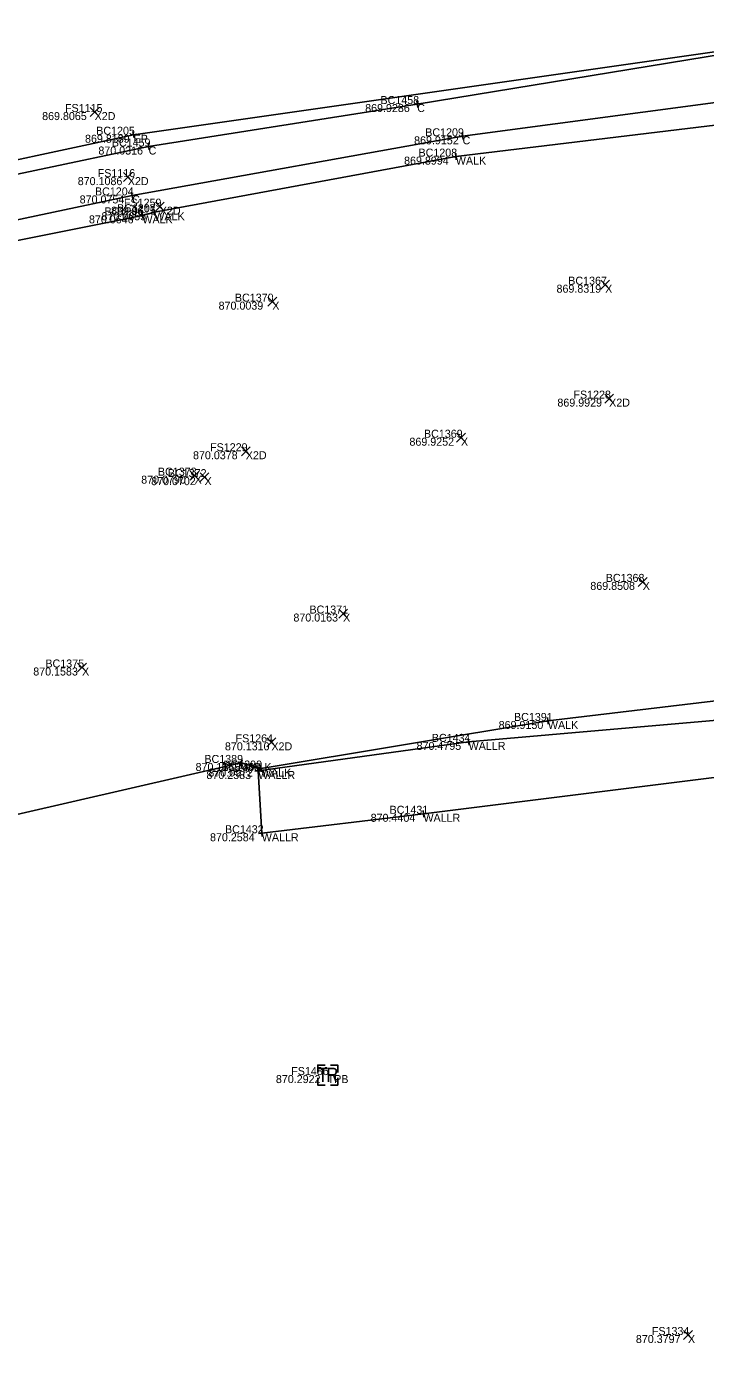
# Model space of a CAD drawing. Extents: x 1479425 to 1480294, y 379351 to 380102.
# Drawn here: x 1479624.01 to 1479629.1, y 379868.13 to 379878.13 of the extents above; entities that cross this region are included whole.
import ezdxf

# ---------------------------------------------------------------- set-up
doc = ezdxf.new("R2010")
doc.units = 0
for name, color, linetype in [('PV_X_Curb', 7, 'Continuous'), ('PV_X_Walk', 7, 'Continuous'), ('RD_X_Wall', 7, 'Continuous'), ('SG_X_PullBox', 7, 'Continuous'), ('SV_X_Random_Point', 7, 'Continuous'), ('SV_X_Shot_Marker', 7, 'Continuous'), ('SV_X_Text_Comment', 7, 'Continuous'), ('SV_X_Text_Elevation', 7, 'Continuous'), ('SV_X_Text_Name', 7, 'Continuous')]:
    doc.layers.add(name, color=color, linetype=linetype)

msp = doc.modelspace()

# ---------------------------------------------------------------- linework, layer by layer
at = {"layer": 'PV_X_Curb'}
for points in [[(1479547.645, 379857.8163), (1479566.743, 379862.6799), (1479585.84, 379867.6329), (1479595.941, 379870.2102), (1479610.1511, 379873.8057), (1479614.8317, 379874.9648), (1479619.4026, 379876.1566), (1479624.8139, 379877.3196), (1479629.6596, 379878.0099), (1479630.6556, 379878.0962), (1479632.7718, 379878.1163), (1479634.4649, 379878.1296), (1479637.7922, 379877.8099), (1479639.1613, 379877.5269), (1479644.7184, 379876.0341), (1479650.0207, 379873.0081)], [(1479674.4002, 379850.8088), (1479663.165, 379861.2618), (1479660.4814, 379863.897), (1479660.3417, 379864.0048), (1479659.4756, 379864.8615), (1479657.9728, 379866.276), (1479656.299, 379867.8605), (1479655.4781, 379868.4849), (1479655.3936, 379868.553), (1479653.3405, 379870.3718), (1479649.8028, 379873.0366), (1479644.8359, 379875.8815), (1479640.9714, 379876.9839), (1479637.7316, 379877.6879), (1479634.8886, 379878.0569), (1479629.5507, 379877.9769), (1479626.9417, 379877.5496), (1479624.927, 379877.2311), (1479623.2196, 379876.8713), (1479619.5522, 379875.9957), (1479615.007, 379874.7968)], [(1479547.62, 379857.3293), (1479567.188, 379862.296), (1479585.958, 379867.1036), (1479596.074, 379869.8004), (1479610.1997, 379873.3276), (1479614.9812, 379874.5289), (1479617.4646, 379875.192), (1479619.4347, 379875.7199), (1479619.5957, 379875.717), (1479622.3222, 379876.3413), (1479624.8041, 379876.8646), (1479627.2818, 379877.3077), (1479629.6031, 379877.6193), (1479629.6735, 379877.6107), (1479631.7805, 379877.7128), (1479634.4106, 379877.6659), (1479636.0794, 379877.5598), (1479637.6114, 379877.382), (1479637.7407, 379877.4038), (1479639.5316, 379877.066), (1479644.5411, 379875.6244), (1479649.735, 379872.6614)]]:
    msp.add_lwpolyline(points, dxfattribs=at)
at = {"layer": 'PV_X_Walk'}
for points in [[(1479648.689, 379868.2743), (1479647.1434, 379869.696), (1479647.0829, 379869.7025), (1479645.8749, 379870.8123), (1479644.5568, 379872.0701), (1479644.4905, 379872.1256), (1479643.2259, 379873.2388), (1479641.9481, 379874.5109), (1479641.8756, 379874.5801), (1479640.4852, 379875.8117), (1479639.2266, 379877.0297), (1479637.7773, 379877.2778), (1479637.6922, 379877.2566), (1479635.9625, 379877.3562), (1479633.5699, 379877.4783), (1479633.687, 379875.5967), (1479633.579, 379875.5311), (1479631.7319, 379875.4802), (1479629.6435, 379875.4272), (1479629.5678, 379877.4383), (1479627.2312, 379877.1555), (1479624.9702, 379876.7386), (1479624.8804, 379876.715), (1479622.4184, 379876.2221)], [(1479639.0409, 379871.8337), (1479638.2687, 379872.4839), (1479637.0974, 379872.9725), (1479637.0508, 379872.9593), (1479635.3514, 379873.1245), (1479633.8033, 379873.1802), (1479633.6601, 379873.2067), (1479631.7248, 379873.2616), (1479629.8147, 379873.1506), (1479629.7038, 379873.1391), (1479627.9217, 379872.925), (1479625.77, 379872.5683), (1479625.6217, 379872.6102), (1479623.1104, 379872.0351)]]:
    msp.add_lwpolyline(points, dxfattribs=at)
at = {"layer": 'RD_X_Wall'}
msp.add_lwpolyline([(1479636.9747, 379872.4267), (1479635.7044, 379872.5174), (1479633.7647, 379872.6014), (1479631.5731, 379872.6491), (1479629.7491, 379872.5728), (1479626.9881, 379872.2291), (1479625.7759, 379872.0832), (1479625.7496, 379872.5499), (1479627.327, 379872.7681), (1479629.7353, 379872.9786), (1479631.9666, 379873.1104), (1479633.7819, 379873.105), (1479635.738, 379872.9618), (1479637.0752, 379872.9151)], close=True, dxfattribs=at)
at = {"layer": 'SG_X_PullBox'}
msp.add_line((1479626.27, 379870.2705), (1479626.27, 379870.2705), dxfattribs=at)
for points in [[(1479626.25, 379870.3455), (1479626.195, 379870.3455), (1479626.195, 379870.2905)], [(1479626.2022, 379870.3205), (1479626.2644, 379870.3205)], [(1479626.2337, 379870.3205), (1479626.2337, 379870.2205)], [(1479626.2756, 379870.2205), (1479626.2756, 379870.3205), (1479626.3134, 379870.3205), (1479626.3173, 379870.3197), (1479626.3228, 379870.3182), (1479626.3252, 379870.3166), (1479626.3276, 379870.315), (1479626.3307, 379870.3111), (1479626.3331, 379870.3071), (1479626.3346, 379870.3008), (1479626.3346, 379870.2914), (1479626.3339, 379870.2882), (1479626.3323, 379870.2835), (1479626.3291, 379870.278), (1479626.326, 379870.2756), (1479626.3236, 379870.2741), (1479626.322, 379870.2733), (1479626.3197, 379870.2725), (1479626.3126, 379870.2717), (1479626.2756, 379870.2717)], [(1479626.345, 379870.2905), (1479626.345, 379870.3455), (1479626.29, 379870.3455)], [(1479626.195, 379870.2505), (1479626.195, 379870.1955), (1479626.25, 379870.1955)], [(1479626.29, 379870.1955), (1479626.345, 379870.1955), (1479626.345, 379870.2505)], [(1479626.3126, 379870.2717), (1479626.3346, 379870.2205)]]:
    msp.add_lwpolyline(points, dxfattribs=at)
at = {"layer": 'SV_X_Random_Point'}
for p, q in [((1479624.4887, 379877.4561), (1479624.5553, 379877.5229)), ((1479624.4887, 379877.5229), (1479624.5553, 379877.4561)), ((1479624.7377, 379876.9684), (1479624.8043, 379877.0352)), ((1479624.7377, 379877.0352), (1479624.8043, 379876.9684)), ((1479624.9777, 379876.7468), (1479625.0443, 379876.8136)), ((1479624.9777, 379876.8136), (1479625.0443, 379876.7468)), ((1479628.3176, 379876.1619), (1479628.3842, 379876.2287)), ((1479628.3176, 379876.2287), (1479628.3842, 379876.1619)), ((1479625.8212, 379876.0349), (1479625.8878, 379876.1017)), ((1479625.8212, 379876.1017), (1479625.8878, 379876.0349)), ((1479628.3477, 379875.3081), (1479628.4143, 379875.3749)), ((1479628.3477, 379875.3749), (1479628.4143, 379875.3081)), ((1479627.2363, 379875.0148), (1479627.3029, 379875.0816)), ((1479627.2363, 379875.0816), (1479627.3029, 379875.0148)), ((1479625.6227, 379874.9135), (1479625.6893, 379874.9803)), ((1479625.6227, 379874.9803), (1479625.6893, 379874.9135)), ((1479625.2387, 379874.7306), (1479625.3053, 379874.7974)), ((1479625.2387, 379874.7974), (1479625.3053, 379874.7306)), ((1479625.3128, 379874.7193), (1479625.3794, 379874.7861)), ((1479625.3128, 379874.7861), (1479625.3794, 379874.7193)), ((1479628.5995, 379873.934), (1479628.6661, 379874.0008)), ((1479628.5995, 379874.0008), (1479628.6661, 379873.934)), ((1479626.3524, 379873.6968), (1479626.419, 379873.7636)), ((1479626.3524, 379873.7636), (1479626.419, 379873.6968)), ((1479624.3947, 379873.2923), (1479624.4613, 379873.3591)), ((1479624.3947, 379873.3591), (1479624.4613, 379873.2923)), ((1479625.8147, 379872.7314), (1479625.8813, 379872.7982)), ((1479625.8147, 379872.7982), (1479625.8813, 379872.7314)), ((1479628.9387, 379868.2883), (1479629.0053, 379868.3551)), ((1479628.9387, 379868.3551), (1479629.0053, 379868.2883))]:
    msp.add_line(p, q, dxfattribs=at)
at = {"layer": 'SV_X_Shot_Marker'}
for p, q in [((1479626.9664, 379877.5537), (1479626.917, 379877.5456)), ((1479626.9457, 379877.5249), (1479626.9377, 379877.5743)), ((1479626.9417, 379877.5496), (1479626.9417, 379877.5496)), ((1479624.7895, 379877.3144), (1479624.8383, 379877.3249)), ((1479624.8086, 379877.3441), (1479624.8191, 379877.2952)), ((1479624.8139, 379877.3196), (1479624.8139, 379877.3196)), ((1479627.2572, 379877.3033), (1479627.3064, 379877.3121)), ((1479627.2774, 379877.3323), (1479627.2862, 379877.2831)), ((1479627.2818, 379877.3077), (1479627.2818, 379877.3077)), ((1479624.9517, 379877.235), (1479624.9023, 379877.2272)), ((1479624.9309, 379877.2064), (1479624.9231, 379877.2558)), ((1479624.927, 379877.2311), (1479624.927, 379877.2311)), ((1479627.256, 379877.1585), (1479627.2064, 379877.1525)), ((1479627.2342, 379877.1307), (1479627.2282, 379877.1803)), ((1479627.2312, 379877.1555), (1479627.2312, 379877.1555)), ((1479624.7796, 379876.8595), (1479624.8286, 379876.8698)), ((1479624.7989, 379876.8891), (1479624.8093, 379876.8402)), ((1479624.8041, 379876.8646), (1479624.8041, 379876.8646)), ((1479624.9046, 379876.7214), (1479624.8562, 379876.7087)), ((1479624.8868, 379876.6908), (1479624.874, 379876.7392)), ((1479624.8804, 379876.715), (1479624.8804, 379876.715)), ((1479624.9948, 379876.7432), (1479624.9456, 379876.7341)), ((1479624.9747, 379876.714), (1479624.9657, 379876.7632)), ((1479624.9702, 379876.7386), (1479624.9702, 379876.7386)), ((1479627.9465, 379872.928), (1479627.8969, 379872.922)), ((1479627.9247, 379872.9002), (1479627.9187, 379872.9498)), ((1479627.9217, 379872.925), (1479627.9217, 379872.925)), ((1479627.3022, 379872.7647), (1479627.3518, 379872.7715)), ((1479627.3236, 379872.7929), (1479627.3304, 379872.7434)), ((1479627.327, 379872.7681), (1479627.327, 379872.7681)), ((1479625.6458, 379872.6034), (1479625.5976, 379872.617)), ((1479625.6149, 379872.5862), (1479625.6285, 379872.6343)), ((1479625.6217, 379872.6102), (1479625.6217, 379872.6102)), ((1479625.7246, 379872.5485), (1479625.7746, 379872.5513)), ((1479625.7947, 379872.5724), (1479625.7453, 379872.5642)), ((1479625.751, 379872.525), (1479625.7482, 379872.5749)), ((1479625.7496, 379872.5499), (1479625.7496, 379872.5499)), ((1479625.7741, 379872.5437), (1479625.7659, 379872.593)), ((1479625.77, 379872.5683), (1479625.77, 379872.5683)), ((1479627.0129, 379872.2322), (1479626.9633, 379872.226)), ((1479626.9912, 379872.2043), (1479626.985, 379872.2539)), ((1479626.9881, 379872.2291), (1479626.9881, 379872.2291)), ((1479625.7789, 379872.0584), (1479625.7729, 379872.108)), ((1479625.8007, 379872.0862), (1479625.7511, 379872.0802)), ((1479625.7759, 379872.0832), (1479625.7759, 379872.0832))]:
    msp.add_line(p, q, dxfattribs=at)

# ---------------------------------------------------------------- texts
at = {"layer": 'SV_X_Text_Comment'}
for s, p in [('C', (1479626.9417, 379877.4896)), ('X2D', (1479624.522, 379877.4295)), ('EP', (1479624.8139, 379877.2596)), ('C', (1479627.2818, 379877.2477)), ('C', (1479624.927, 379877.1711)), ('WALK', (1479627.2312, 379877.0955)), ('X2D', (1479624.771, 379876.9418)), ('C', (1479624.8041, 379876.8046)), ('WALK', (1479624.8804, 379876.655)), ('WALK', (1479624.9702, 379876.6786)), ('X2D', (1479625.011, 379876.7202)), ('X', (1479628.3509, 379876.1353)), ('X', (1479625.8545, 379876.0083)), ('X2D', (1479628.381, 379875.2815)), ('X', (1479627.2696, 379874.9882)), ('X2D', (1479625.656, 379874.8869)), ('X', (1479625.272, 379874.704)), ('X', (1479625.3461, 379874.6927)), ('X', (1479628.6328, 379873.9074)), ('X', (1479626.3857, 379873.6702)), ('X', (1479624.428, 379873.2657)), ('WALK', (1479627.9217, 379872.865)), ('X2D', (1479625.848, 379872.7048)), ('WALLR', (1479627.327, 379872.7081)), ('WALK', (1479625.6217, 379872.5502)), ('WALLR', (1479625.7496, 379872.4899)), ('WALK', (1479625.77, 379872.5083)), ('WALLR', (1479626.9881, 379872.1691)), ('WALLR', (1479625.7759, 379872.0232)), ('TPB', (1479626.27, 379870.2105)), ('X', (1479628.972, 379868.2617))]:
    msp.add_text(s, height=0.06, dxfattribs=at).set_placement(p)
at = {"layer": 'SV_X_Text_Elevation'}
for s, p in [('869.9286', (1479626.551, 379877.4896)), ('869.8065', (1479624.1285, 379877.4295)), ('869.8189', (1479624.4502, 379877.2596)), ('869.9152', (1479626.9181, 379877.2477)), ('870.0316', (1479624.5505, 379877.1711)), ('869.8994', (1479626.8429, 379877.0955)), ('870.1086', (1479624.3955, 379876.9418)), ('870.0754', (1479624.4101, 379876.8046)), ('870.0646', (1479624.4798, 379876.655)), ('870.0655', (1479624.5738, 379876.6786)), ('869.9615', (1479624.6459, 379876.7202)), ('869.8319', (1479627.9862, 379876.1353)), ('870.0039', (1479625.452, 379876.0083)), ('869.9929', (1479627.9927, 379875.2815)), ('869.9252', (1479626.8832, 379874.9882)), ('870.0378', (1479625.2601, 379874.8869)), ('870.0790', (1479624.8714, 379874.704)), ('870.0702', (1479624.9464, 379874.6927)), ('869.8508', (1479628.2397, 379873.9074)), ('870.0163', (1479626.013, 379873.6702)), ('870.1583', (1479624.0619, 379873.2657)), ('869.9150', (1479627.5523, 379872.865)), ('870.1310', (1479625.4994, 379872.7048)), ('870.4795', (1479626.9368, 379872.7081)), ('870.1155', (1479625.2793, 379872.5502)), ('870.2583', (1479625.3608, 379872.4899)), ('870.0972', (1479625.3751, 379872.5083)), ('870.4404', (1479626.5922, 379872.1691)), ('870.2584', (1479625.3876, 379872.0232)), ('870.2922', (1479625.8817, 379870.2105)), ('870.3797', (1479628.5813, 379868.2617))]:
    msp.add_text(s, height=0.06, dxfattribs=at).set_placement(p)
at = {"layer": 'SV_X_Text_Name'}
for s, p in [('BC1458', (1479626.6658, 379877.5496)), ('FS1115', (1479624.3001, 379877.4895)), ('BC1205', (1479624.5343, 379877.3196)), ('BC1209', (1479627.0017, 379877.3077)), ('BC1459', (1479624.6511, 379877.2311)), ('BC1208', (1479626.9511, 379877.1555)), ('FS1116', (1479624.5453, 379877.0018)), ('BC1204', (1479624.5249, 379876.8646)), ('BC1207', (1479624.6906, 379876.7386)), ('FS1259', (1479624.7422, 379876.7802)), ('BC1206', (1479624.597, 379876.715)), ('BC1367', (1479628.0741, 379876.1953)), ('BC1370', (1479625.5744, 379876.0683)), ('FS1228', (1479628.1132, 379875.3415)), ('BC1369', (1479626.9923, 379875.0482)), ('FS1229', (1479625.3882, 379874.9469)), ('BC1373', (1479624.9971, 379874.764)), ('BC1372', (1479625.0717, 379874.7527)), ('BC1368', (1479628.3555, 379873.9674)), ('BC1371', (1479626.1333, 379873.7302)), ('BC1375', (1479624.1531, 379873.3257)), ('BC1391', (1479627.6675, 379872.925)), ('FS1264', (1479625.5792, 379872.7648)), ('BC1434', (1479627.0511, 379872.7681)), ('BC1389', (1479625.3454, 379872.6102)), ('BC1433', (1479625.4733, 379872.5499)), ('BC1390', (1479625.488, 379872.5683)), ('BC1431', (1479626.7343, 379872.2291)), ('BC1432', (1479625.5, 379872.0832)), ('FS1486', (1479625.9965, 379870.2705)), ('FS1334', (1479628.7013, 379868.3217))]:
    msp.add_text(s, height=0.06, dxfattribs=at).set_placement(p)

doc.saveas('drawing.dxf')
